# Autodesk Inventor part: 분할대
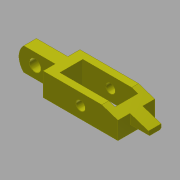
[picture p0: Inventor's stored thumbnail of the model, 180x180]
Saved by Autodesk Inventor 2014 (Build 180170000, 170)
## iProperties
Created: 2016-11
Part Number: 분할대
Material: 강철, 연강
Document SubType Name: Modeling
Designer: mduedu
Density: 1 g/cm^3
Appearance: 노란색
Author: mduedu
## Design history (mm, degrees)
sketch "스케치1"
  geometry: L1 (32.5, 16)-(-32.5, 16); L2 (-32.5, 16)-(-32.5, -16); L3 (-32.5, -16)-(32.5, -16); L4 (32.5, -16)-(32.5, 16); L5 (24, 10)-(-24, 10); L6 (-24, 10)-(-24, -10); L7 (-24, -10)-(24, -10); L8 (24, -10)-(24, 10); L9 (24, 0)-(-24, 0); L10 (0, -16)-(0, 16); 4 further points
  constraints: 20 end point, 7 midpoint, 4 parallel, 2 coincident, 2 horizontal, 2 perpendicular, 1 horizontal alignment
  dimensions: "d0" = 20 distance of L5.end L6.end; "d2" = 32 distance between parallel lines of L1 L3; "d3" = 48 distance of L5.start L5.end; "d4" = 65 distance of L1.start L1.end
extrude "돌출1" new body sketch "스케치1" distance "d5" = 20; taper "d6" = 0 deg
sketch "스케치2"
  geometry: L1 (0, 0)-(65, 0) reference; L2 (65, 0)-(65, 20) reference; L3 (0, 20)-(65, 20) reference; L4 (0, 0)-(0, 20) reference; L5 (32.5, 0)-(32.5, 20); C1 r 4 at (32.5, 10)
  constraints: 2 end point, 2 midpoint, 1 centre point
  dimensions: "d7" = 8 diameter of C1
extrude "돌출2" cut sketch "스케치2" stored distance "d8" = 20; taper "d9" = 0 deg
chamfer "모따기1" distance "d10" = 0.2; stored, may be unused: second distance "d11" = 2, angle "d12" = 45 deg
sketch "스케치3"
  geometry: L1 (-32.5, 0)-(-32.5, 20) reference; L2 (-32.5, 20)-(-59.798, 20); L3 (-64, 20)-(-64, 0); L4 (-64, 0)-(-59.798, 0); L5 (-32.5, 0)-(-32.5, 20); L6 (-59.798, 20)-(-64, 20); L7 (-59.798, 0)-(-32.5, 0); C1 r 4.2 at (0, 10) reference; C2 r 5 at (-50, 10); A1 r 14 centre (-50, 10) between (-59.798, 20) and (-59.798, 0); 1 further point
  constraints: 12 end point, 5 parallel, 2 centre point, 2 horizontal, 2 perpendicular, 2 point on circle, 1 coincident, 1 horizontal alignment, 1 tangent
  dimensions: "d13" = 64 distance from line of L3 C1.centre; "d14" = 14 radius of A1; "d15" = 10 diameter of C2
extrude "돌출3" join sketch "스케치3" stored distance "d16" = 11; taper "d17" = 0 deg
sketch "스케치4"
  geometry: L1 (32.5, 0)-(32.5, 20) reference; L2 (32.5, 20)-(48.5, 20); L3 (48.5, 20)-(48.5, 6); L4 (48.5, 6)-(32.5, 6); L5 (32.5, 6)-(32.5, 20); L6 (32.5, 0)-(-32.5, 0) reference; 1 further point
  constraints: 8 end point, 2 parallel, 1 horizontal, 1 perpendicular
  dimensions: "d18" = 16 distance of L1.end L2.end; "d19" = 6 distance between parallel lines of L4 L6
extrude "돌출4" join sketch "스케치4" stored distance "d20" = 11; taper "d21" = 0 deg
chamfer "모따기2" distance "d22" = 30; stored, may be unused: second distance "d23" = 10, angle "d24" = 45 deg
chamfer "모따기3" distance "d25" = 1; stored, may be unused: second distance "d26" = 10, angle "d27" = 45 deg
chamfer "모따기4" distance "d28" = 0.2; stored, may be unused: second distance "d29" = 10, angle "d30" = 45 deg
node "솔리드1"
node "투영된 루프1"
